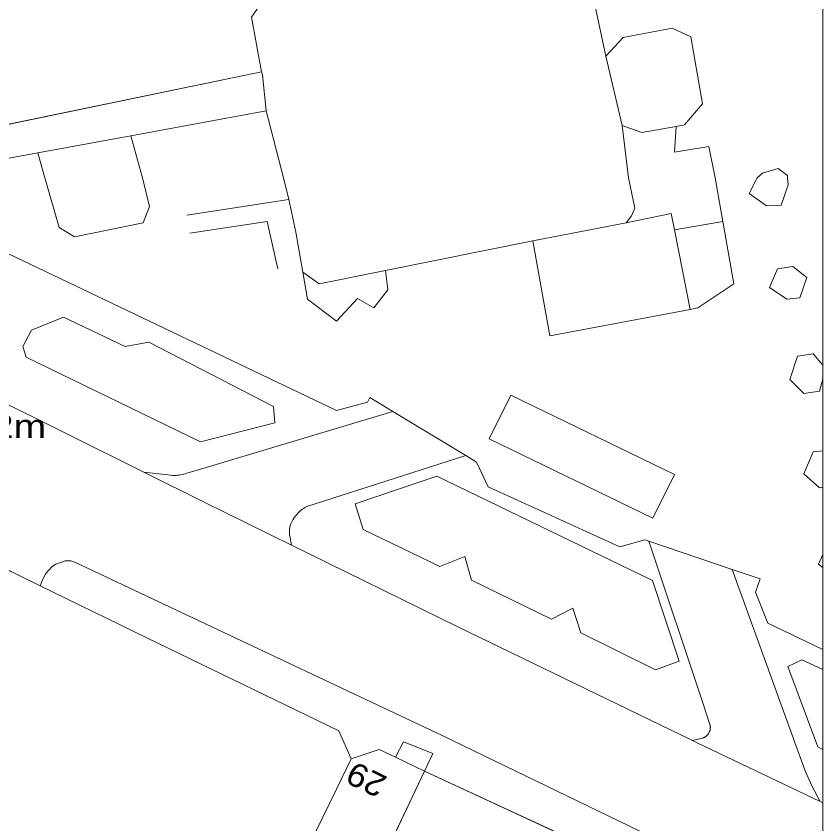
# Model space of a CAD drawing. Extents: x 528790 to 529292, y 179350 to 179856.
# Drawn here: x 529238.4 to 529290.2, y 179458.5 to 179510.4 of the extents above; entities that cross this region are included whole.
import ezdxf

# ---------------------------------------------------------------- set-up
doc = ezdxf.new("R2010")
doc.units = 0
doc.header["$LTSCALE"] = 0.6
for name, color, linetype, lineweight in [('1', 7, 'Continuous', 13), ('2', 7, 'Continuous', 13), ('7', 7, 'Continuous', 13)]:
    doc.layers.add(name, color=color, linetype=linetype, lineweight=lineweight)
doc.layers.add('5', color=7, linetype='Continuous')

msp = doc.modelspace()

# ---------------------------------------------------------------- linework, layer by layer
at = {"layer": '1'}
for points in [[(529290.22, 179480.144), (529290, 179480.1), (529289, 179481), (529289.6, 179482.4), (529290.22, 179482.462), (529290.22, 179487.099), (529290, 179486.3), (529289, 179486.15), (529288.1, 179487.05), (529288.6, 179488.55), (529289.6, 179488.7), (529290.22, 179487.963), (529290.22, 179512.837)], [(529236.8, 179503.2), (529254.2, 179506.8), (529253.55, 179510.3), (529254, 179510.95)], [(529254, 179510.95), (529253.55, 179510.3), (529254.2, 179506.8), (529254.25, 179506.6), (529254.5, 179504.3), (529255.6, 179500), (529255.95, 179498.6), (529256.4, 179496.5), (529256.85, 179493.95), (529257.9, 179493.2), (529262.15, 179494.05), (529271.6, 179495.95), (529277.6, 179497.1), (529277.95, 179497.55), (529278.15, 179498.05), (529277.75, 179500), (529277.35, 179503.35), (529276.3, 179507.8), (529275.7, 179510.6)], [(529275.7, 179510.6), (529276.3, 179507.8), (529277.4, 179509), (529280.55, 179509.6), (529281.75, 179509.05), (529282.5, 179504.75), (529281.35, 179503.4), (529280.8, 179503.3), (529280.7, 179501.65), (529281.35, 179501.75), (529282.9, 179502), (529283.3, 179500), (529283.4, 179499.5), (529283.8, 179497.2), (529284.5, 179493.2), (529282.2, 179491.65), (529281.7, 179491.55), (529272.7, 179489.85), (529271.6, 179495.95), (529262.15, 179494.05), (529262.3, 179492.8), (529261.4, 179491.65), (529260.35, 179492.25), (529259, 179490.8), (529257.15, 179492.2), (529256.85, 179493.95), (529256.4, 179496.5), (529255.95, 179498.6), (529255.6, 179500), (529254.5, 179504.3), (529245.8, 179502.7), (529246.55, 179500), (529247, 179498.15), (529246.6, 179497.1), (529242.2, 179496.2), (529241.2, 179496.8), (529240.3, 179500), (529239.85, 179501.6), (529235.2, 179500.75)], [(529233.6, 179497.2), (529259, 179485.05), (529261, 179485.6), (529261.15, 179485.9), (529262.63, 179485.003), (529267.306, 179482.17), (529268, 179481.75), (529268.75, 179480.15), (529277.2, 179476.3), (529278.8, 179476.75)], [(529236.7, 179486.05), (529246.643, 179481.097), (529248.385, 179480.899), (529248.482, 179480.892), (529248.579, 179480.89), (529248.716, 179480.893), (529248.813, 179480.901), (529248.91, 179480.912), (529249.006, 179480.928), (529249.101, 179480.947), (529249.196, 179480.971), (529249.289, 179480.998), (529249.406, 179481.038), (529250.208, 179481.278), (529262.63, 179485.003), (529261.15, 179485.9), (529261, 179485.6), (529259, 179485.05), (529233.6, 179497.2)], [(529290.22, 179452.774), (529290.22, 179459.873), (529290.053, 179459.953), (529282.2, 179463.7), (529281.852, 179463.869), (529266.75, 179471.2), (529256.119, 179476.417), (529250.55, 179479.15), (529246.643, 179481.097), (529236.7, 179486.05)], [(529278.8, 179476.75), (529279.06, 179476.662), (529284.405, 179474.857), (529286.2, 179474.25), (529285.9, 179473.4), (529286.7, 179471.4), (529290.22, 179469.708), (529290.22, 179474.977), (529289.95, 179475.2), (529290.22, 179475.808), (529290.22, 179480.144)], [(529255.002, 179452.549), (529259, 179460.75), (529259.95, 179462.7), (529259.15, 179464.5), (529246.844, 179470.476), (529240, 179473.8), (529236.4, 179475.55), (529234.9, 179472.4), (529229.655, 179460.856), (529228.098, 179457.563)], [(529236.4, 179475.55), (529240, 179473.8), (529240.15, 179474.2), (529240.35, 179474.6), (529240.55, 179474.8), (529240.75, 179475.05), (529241, 179475.2), (529241.6, 179475.4), (529241.95, 179475.4), (529242.25, 179475.3), (529265.8, 179464.2), (529281.8, 179456.45)], [(529281.8, 179456.45), (529265.8, 179464.2), (529242.25, 179475.3), (529241.95, 179475.4), (529241.6, 179475.4), (529241, 179475.2), (529240.75, 179475.05), (529240.55, 179474.8), (529240.35, 179474.6), (529240.15, 179474.2), (529240, 179473.8), (529246.844, 179470.476), (529259.15, 179464.5), (529259.95, 179462.7), (529261.75, 179463.3), (529262.8, 179462.8), (529263.3, 179463.8), (529265.2, 179463.05), (529264.65, 179461.9), (529284.55, 179452.7)]]:
    msp.add_lwpolyline(points, dxfattribs=at)
for points in [[(529280.8, 179503.3), (529281.35, 179503.4), (529282.5, 179504.75), (529281.75, 179509.05), (529280.55, 179509.6), (529277.4, 179509), (529276.3, 179507.8), (529277.35, 179503.35), (529278.6, 179502.9)], [(529239.85, 179501.6), (529245.8, 179502.7), (529254.5, 179504.3), (529254.25, 179506.6), (529254.2, 179506.8), (529236.8, 179503.2), (529235.8, 179503), (529234.8, 179507.8), (529233.9, 179507.65), (529231.45, 179507.15), (529228.15, 179506.5), (529229.25, 179500.7), (529229.4, 179500), (529229.8, 179499), (529232.6, 179497.8), (529234.15, 179498.15), (529234.2, 179497.9), (529234.35, 179497.15), (529235.9, 179497.3), (529235.4, 179500), (529235.2, 179500.75)], [(529283.8, 179497.2), (529283.4, 179499.5), (529283.3, 179500), (529282.9, 179502), (529281.35, 179501.75), (529280.7, 179501.65), (529280.8, 179503.3), (529278.6, 179502.9), (529277.35, 179503.35), (529277.75, 179500), (529278.15, 179498.05), (529277.95, 179497.55), (529277.6, 179497.1), (529280.49, 179497.7), (529280.7, 179496.65)], [(529246.6, 179497.1), (529247, 179498.15), (529246.55, 179500), (529245.8, 179502.7), (529239.85, 179501.6), (529240.3, 179500), (529241.2, 179496.8), (529242.2, 179496.2)], [(529286, 179500), (529285.5, 179499), (529286.6, 179498.2), (529287.55, 179498.25), (529288, 179499.55), (529287.95, 179500), (529287.95, 179500.15), (529287.35, 179500.6), (529286.35, 179500.3)], [(529285.5, 179499), (529286, 179500), (529286.35, 179500.3), (529287.35, 179500.6), (529287.95, 179500.15), (529287.95, 179500), (529288, 179499.55), (529287.55, 179498.25), (529286.6, 179498.2)], [(529272.7, 179489.85), (529281.7, 179491.55), (529280.7, 179496.65), (529280.49, 179497.7), (529277.6, 179497.1), (529271.6, 179495.95)], [(529280.7, 179496.65), (529281.7, 179491.55), (529282.2, 179491.65), (529284.5, 179493.2), (529283.8, 179497.2)], [(529262.15, 179494.05), (529257.9, 179493.2), (529256.85, 179493.95), (529257.15, 179492.2), (529259, 179490.8), (529260.35, 179492.25), (529261.4, 179491.65), (529262.3, 179492.8)], [(529288.75, 179492.3), (529289.2, 179493.6), (529288.3, 179494.3), (529287.3, 179494.15), (529286.8, 179492.95), (529287.9, 179492.2)], [(529286.8, 179492.95), (529287.3, 179494.15), (529288.3, 179494.3), (529289.2, 179493.6), (529288.75, 179492.3), (529287.9, 179492.2)], [(529241.491, 179491.057), (529239.425, 179490.207), (529238.882, 179489.164), (529239.096, 179488.475), (529250.285, 179483.053), (529255.045, 179484.276), (529254.966, 179485.313), (529246.971, 179489.452), (529245.452, 179489.16)], [(529241.491, 179491.057), (529245.452, 179489.16), (529246.971, 179489.452), (529254.966, 179485.313), (529255.045, 179484.276), (529250.285, 179483.053), (529239.096, 179488.475), (529238.882, 179489.164), (529239.425, 179490.207)], [(529290.22, 179487.963), (529289.6, 179488.7), (529288.6, 179488.55), (529288.1, 179487.05), (529289, 179486.15), (529290, 179486.3), (529290.22, 179487.099)], [(529270.2, 179486.05), (529280.7, 179480.95), (529279.3, 179478.15), (529268.8, 179483.25)], [(529279.3, 179478.15), (529280.7, 179480.95), (529270.2, 179486.05), (529268.8, 179483.25)], [(529267.306, 179482.17), (529262.63, 179485.003), (529250.208, 179481.278), (529249.406, 179481.038), (529249.289, 179480.998), (529249.196, 179480.971), (529249.101, 179480.947), (529249.006, 179480.928), (529248.91, 179480.912), (529248.813, 179480.901), (529248.716, 179480.893), (529248.579, 179480.89), (529248.482, 179480.892), (529248.385, 179480.899), (529246.643, 179481.097), (529250.55, 179479.15), (529256.119, 179476.417), (529256.005, 179477.017), (529255.996, 179477.08), (529255.99, 179477.143), (529255.986, 179477.207), (529255.985, 179477.271), (529255.987, 179477.334), (529255.991, 179477.398), (529255.998, 179477.461), (529256.008, 179477.524), (529256.02, 179477.587), (529256.035, 179477.649), (529256.052, 179477.71), (529256.078, 179477.785), (529256.116, 179477.875), (529256.16, 179477.962), (529256.21, 179478.047), (529256.316, 179478.205), (529256.375, 179478.283), (529256.436, 179478.359), (529256.501, 179478.433), (529256.569, 179478.503), (529256.64, 179478.571), (529256.714, 179478.635), (529256.79, 179478.697), (529256.869, 179478.755), (529256.95, 179478.81), (529257.104, 179478.902)], [(529290.22, 179480.144), (529290.22, 179482.462), (529289.6, 179482.4), (529289, 179481), (529290, 179480.1)], [(529268, 179481.75), (529267.306, 179482.17), (529257.104, 179478.902), (529256.95, 179478.81), (529256.869, 179478.755), (529256.79, 179478.697), (529256.714, 179478.635), (529256.64, 179478.571), (529256.569, 179478.503), (529256.501, 179478.433), (529256.436, 179478.359), (529256.375, 179478.283), (529256.316, 179478.205), (529256.21, 179478.047), (529256.16, 179477.962), (529256.116, 179477.875), (529256.078, 179477.785), (529256.052, 179477.71), (529256.035, 179477.649), (529256.02, 179477.587), (529256.008, 179477.524), (529255.998, 179477.461), (529255.991, 179477.398), (529255.987, 179477.334), (529255.985, 179477.271), (529255.986, 179477.207), (529255.99, 179477.143), (529255.996, 179477.08), (529256.005, 179477.017), (529256.119, 179476.417), (529266.75, 179471.2), (529281.852, 179463.869), (529282.477, 179464.019), (529282.506, 179464.028), (529282.536, 179464.039), (529282.565, 179464.051), (529282.593, 179464.064), (529282.621, 179464.078), (529282.648, 179464.093), (529282.675, 179464.11), (529282.7, 179464.127), (529282.725, 179464.146), (529282.749, 179464.166), (529282.773, 179464.187), (529282.795, 179464.209), (529282.817, 179464.231), (529282.837, 179464.255), (529282.857, 179464.279), (529282.875, 179464.305), (529282.892, 179464.331), (529282.908, 179464.358), (529282.927, 179464.394), (529282.94, 179464.422), (529282.952, 179464.451), (529282.962, 179464.481), (529282.972, 179464.511), (529282.98, 179464.541), (529282.986, 179464.571), (529282.992, 179464.602), (529282.996, 179464.633), (529282.998, 179464.664), (529283, 179464.695), (529283, 179464.727), (529282.998, 179464.758), (529282.996, 179464.789), (529282.992, 179464.82), (529282.986, 179464.851), (529282.98, 179464.881), (529282.972, 179464.911), (529282.534, 179466.227), (529279.06, 179476.662), (529278.8, 179476.75), (529277.2, 179476.3), (529268.75, 179480.15)], [(529260.716, 179477.416), (529260.215, 179479.071), (529265.454, 179480.852), (529279.283, 179474.142), (529280.995, 179468.972), (529279.479, 179468.404), (529274.683, 179470.777), (529274.183, 179472.363), (529272.807, 179471.657), (529267.664, 179474.165), (529267.234, 179475.683), (529265.65, 179475.044)], [(529265.454, 179480.852), (529260.215, 179479.071), (529260.716, 179477.416), (529265.65, 179475.044), (529267.234, 179475.683), (529267.664, 179474.165), (529272.807, 179471.657), (529274.183, 179472.363), (529274.683, 179470.777), (529279.479, 179468.404), (529280.995, 179468.972), (529279.283, 179474.142)], [(529289.512, 179460.965), (529289.087, 179461.929), (529288.596, 179463.286), (529284.405, 179474.857), (529279.06, 179476.662), (529282.534, 179466.227), (529282.972, 179464.911), (529282.98, 179464.881), (529282.986, 179464.851), (529282.992, 179464.82), (529282.996, 179464.789), (529282.998, 179464.758), (529283, 179464.727), (529283, 179464.695), (529282.998, 179464.664), (529282.996, 179464.633), (529282.992, 179464.602), (529282.986, 179464.571), (529282.98, 179464.541), (529282.972, 179464.511), (529282.962, 179464.481), (529282.952, 179464.451), (529282.94, 179464.422), (529282.927, 179464.394), (529282.908, 179464.358), (529282.892, 179464.331), (529282.875, 179464.305), (529282.857, 179464.279), (529282.837, 179464.255), (529282.817, 179464.231), (529282.795, 179464.209), (529282.773, 179464.187), (529282.749, 179464.166), (529282.725, 179464.146), (529282.7, 179464.127), (529282.675, 179464.11), (529282.648, 179464.093), (529282.621, 179464.078), (529282.593, 179464.064), (529282.565, 179464.051), (529282.536, 179464.039), (529282.506, 179464.028), (529282.477, 179464.019), (529281.852, 179463.869), (529282.2, 179463.7), (529290.053, 179459.953)], [(529290.22, 179474.977), (529290.22, 179475.808), (529289.95, 179475.2)], [(529290.22, 179459.873), (529290.22, 179463.302), (529289.902, 179463.459), (529287.983, 179468.627), (529288.878, 179469.051), (529290.22, 179468.424), (529290.22, 179469.708), (529286.7, 179471.4), (529285.9, 179473.4), (529286.2, 179474.25), (529284.405, 179474.857), (529288.596, 179463.286), (529289.087, 179461.929), (529289.512, 179460.965), (529290.053, 179459.953)], [(529290.22, 179463.302), (529290.22, 179468.424), (529288.878, 179469.051), (529287.983, 179468.627), (529289.902, 179463.459)], [(529264.65, 179461.9), (529265.2, 179463.05), (529263.3, 179463.8), (529262.8, 179462.8)], [(529262.8, 179462.8), (529261.75, 179463.3), (529259.95, 179462.7), (529259, 179460.75), (529255.002, 179452.549), (529254.218, 179450.942), (529253.448, 179449.363), (529249.795, 179441.859), (529246.7, 179435.5), (529251.2, 179433.4), (529253.35, 179438), (529264.65, 179461.9)], [(529285.8, 179449.3), (529284.55, 179452.7), (529264.65, 179461.9), (529253.35, 179438), (529258.8, 179435.6), (529263.3, 179433.55), (529264.2, 179435.55), (529265.6, 179434.9), (529266, 179435.7), (529267.4, 179435.05), (529267, 179434.25), (529271.4, 179432.25), (529273.9, 179431.15), (529280.4, 179439.3), (529279.75, 179439.65), (529280.2, 179439.8), (529280.7, 179440.25), (529280.95, 179440.45), (529281.3, 179440.8), (529281.4, 179441.15), (529281.6, 179441.45), (529281.6, 179442.5), (529282.35, 179442.1)]]:
    msp.add_lwpolyline(points, close=True, dxfattribs=at)
at = {"layer": '2'}
for p, q in [((529276.3, 179507.8), (529277.35, 179503.35)), ((529236.8, 179503.2), (529254.2, 179506.8)), ((529254.25, 179506.6), (529254.2, 179506.8)), ((529254.5, 179504.3), (529254.25, 179506.6)), ((529254.5, 179504.3), (529245.8, 179502.7)), ((529245.8, 179502.7), (529239.85, 179501.6)), ((529255.95, 179498.6), (529249.4, 179497.6)), ((529255.95, 179498.6), (529256.4, 179496.5)), ((529277.6, 179497.1), (529271.6, 179495.95)), ((529283.8, 179497.2), (529280.7, 179496.65)), ((529256.85, 179493.95), (529256.4, 179496.5)), ((529280.7, 179496.65), (529281.7, 179491.55)), ((529271.6, 179495.95), (529262.15, 179494.05)), ((529267.306, 179482.17), (529262.63, 179485.003)), ((529290.22, 179480.144), (529290, 179480.1)), ((529284.405, 179474.857), (529279.06, 179476.662)), ((529236.4, 179475.55), (529240, 179473.8)), ((529262.8, 179462.8), (529264.65, 179461.9)), ((529264.65, 179461.9), (529253.35, 179438)), ((529264.65, 179461.9), (529284.55, 179452.7)), ((529290.053, 179459.953), (529290.22, 179459.873))]:
    msp.add_line(p, q, dxfattribs=at)
for points in [[(529254.2, 179506.8), (529253.55, 179510.3), (529254, 179510.95), (529264.9, 179513.05), (529264.75, 179514.15), (529268, 179514.7), (529268.2, 179513.6), (529274.35, 179514.9), (529274.6, 179514.8), (529274.75, 179514.7), (529274.8, 179514.55), (529275.7, 179510.6), (529276.3, 179507.8)], [(529276.3, 179507.8), (529277.4, 179509), (529280.55, 179509.6), (529281.75, 179509.05), (529282.5, 179504.75), (529281.35, 179503.4), (529280.8, 179503.3)], [(529254.5, 179504.3), (529255.6, 179500), (529255.95, 179498.6)], [(529277.35, 179503.35), (529277.75, 179500), (529278.15, 179498.05), (529277.95, 179497.55), (529277.6, 179497.1)], [(529280.8, 179503.3), (529278.6, 179502.9), (529277.35, 179503.35)], [(529283.8, 179497.2), (529283.4, 179499.5), (529283.3, 179500), (529282.9, 179502), (529281.35, 179501.75), (529280.7, 179501.65), (529280.8, 179503.3)], [(529239.85, 179501.6), (529240.3, 179500), (529241.2, 179496.8), (529242.2, 179496.2), (529246.6, 179497.1), (529247, 179498.15), (529246.55, 179500), (529245.8, 179502.7)], [(529239.85, 179501.6), (529235.2, 179500.75), (529235.4, 179500), (529235.9, 179497.3), (529234.35, 179497.15), (529234.2, 179497.9)], [(529262.63, 179485.003), (529261.15, 179485.9), (529261, 179485.6), (529259, 179485.05), (529233.6, 179497.2), (529234.2, 179497.9)], [(529280.7, 179496.65), (529280.49, 179497.7), (529277.6, 179497.1)], [(529249.6, 179496.45), (529254.55, 179497.2), (529255.25, 179494.15)], [(529283.8, 179497.2), (529284.5, 179493.2), (529282.2, 179491.65), (529281.7, 179491.55)], [(529281.7, 179491.55), (529272.7, 179489.85), (529271.6, 179495.95)], [(529262.15, 179494.05), (529262.3, 179492.8), (529261.4, 179491.65), (529260.35, 179492.25), (529259, 179490.8), (529257.15, 179492.2), (529256.85, 179493.95)], [(529262.15, 179494.05), (529257.9, 179493.2), (529256.85, 179493.95)], [(529222.455, 179493.382), (529225.55, 179491.8), (529236.7, 179486.05), (529246.643, 179481.097)], [(529289, 179486.15), (529288.1, 179487.05), (529288.6, 179488.55), (529289.6, 179488.7), (529290.22, 179487.963)], [(529290.22, 179487.099), (529290, 179486.3), (529289, 179486.15)], [(529246.643, 179481.097), (529248.385, 179480.899), (529248.482, 179480.892), (529248.579, 179480.89), (529248.716, 179480.893), (529248.813, 179480.901), (529248.91, 179480.912), (529249.006, 179480.928), (529249.101, 179480.947), (529249.196, 179480.971), (529249.289, 179480.998), (529249.406, 179481.038), (529250.208, 179481.278), (529262.63, 179485.003)], [(529290, 179480.1), (529289, 179481), (529289.6, 179482.4), (529290.22, 179482.462)], [(529256.119, 179476.417), (529256.005, 179477.017), (529255.996, 179477.08), (529255.99, 179477.143), (529255.986, 179477.207), (529255.985, 179477.271), (529255.987, 179477.334), (529255.991, 179477.398), (529255.998, 179477.461), (529256.008, 179477.524), (529256.02, 179477.587), (529256.035, 179477.649), (529256.052, 179477.71), (529256.078, 179477.785), (529256.116, 179477.875), (529256.16, 179477.962), (529256.21, 179478.047), (529256.316, 179478.205), (529256.375, 179478.283), (529256.436, 179478.359), (529256.501, 179478.433), (529256.569, 179478.503), (529256.64, 179478.571), (529256.714, 179478.635), (529256.79, 179478.697), (529256.869, 179478.755), (529256.95, 179478.81), (529257.104, 179478.902), (529267.306, 179482.17)], [(529279.06, 179476.662), (529278.8, 179476.75), (529277.2, 179476.3), (529268.75, 179480.15), (529268, 179481.75), (529267.306, 179482.17)], [(529246.643, 179481.097), (529250.55, 179479.15), (529256.119, 179476.417)], [(529256.119, 179476.417), (529266.75, 179471.2), (529281.852, 179463.869)], [(529279.06, 179476.662), (529282.534, 179466.227), (529282.972, 179464.911), (529282.98, 179464.881), (529282.986, 179464.851), (529282.992, 179464.82), (529282.996, 179464.789), (529282.998, 179464.758), (529283, 179464.727), (529283, 179464.695), (529282.998, 179464.664), (529282.996, 179464.633), (529282.992, 179464.602), (529282.986, 179464.571), (529282.98, 179464.541), (529282.972, 179464.511), (529282.962, 179464.481), (529282.952, 179464.451), (529282.94, 179464.422), (529282.927, 179464.394), (529282.908, 179464.358), (529282.892, 179464.331), (529282.875, 179464.305), (529282.857, 179464.279), (529282.837, 179464.255), (529282.817, 179464.231), (529282.795, 179464.209), (529282.773, 179464.187), (529282.749, 179464.166), (529282.725, 179464.146), (529282.7, 179464.127), (529282.675, 179464.11), (529282.648, 179464.093), (529282.621, 179464.078), (529282.593, 179464.064), (529282.565, 179464.051), (529282.536, 179464.039), (529282.506, 179464.028), (529282.477, 179464.019), (529281.852, 179463.869)], [(529290.22, 179474.977), (529289.95, 179475.2), (529290.22, 179475.808)], [(529240, 179473.8), (529240.15, 179474.2), (529240.35, 179474.6), (529240.55, 179474.8), (529240.75, 179475.05), (529241, 179475.2), (529241.6, 179475.4), (529241.95, 179475.4), (529242.25, 179475.3), (529265.8, 179464.2), (529281.8, 179456.45), (529289.2, 179453), (529289.4, 179452.8), (529289.6, 179452.65), (529289.75, 179452.5), (529289.95, 179452.2)], [(529284.405, 179474.857), (529288.596, 179463.286), (529289.087, 179461.929), (529289.512, 179460.965), (529290.053, 179459.953)], [(529290.22, 179469.708), (529286.7, 179471.4), (529285.9, 179473.4), (529286.2, 179474.25), (529284.405, 179474.857)], [(529259.95, 179462.7), (529259.15, 179464.5), (529246.844, 179470.476), (529240, 179473.8)], [(529290.22, 179463.302), (529289.902, 179463.459), (529287.983, 179468.627), (529288.878, 179469.051), (529290.22, 179468.424)], [(529262.8, 179462.8), (529263.3, 179463.8), (529265.2, 179463.05), (529264.65, 179461.9)], [(529281.852, 179463.869), (529282.2, 179463.7), (529290.053, 179459.953)], [(529259.95, 179462.7), (529261.75, 179463.3), (529262.8, 179462.8)], [(529246.7, 179435.5), (529249.795, 179441.859), (529253.448, 179449.363), (529254.218, 179450.942), (529255.002, 179452.549), (529259, 179460.75), (529259.95, 179462.7)]]:
    msp.add_lwpolyline(points, dxfattribs=at)
for points in [[(529286, 179500), (529285.5, 179499), (529286.6, 179498.2), (529287.55, 179498.25), (529288, 179499.55), (529287.95, 179500), (529287.95, 179500.15), (529287.35, 179500.6), (529286.35, 179500.3)], [(529288.75, 179492.3), (529287.9, 179492.2), (529286.8, 179492.95), (529287.3, 179494.15), (529288.3, 179494.3), (529289.2, 179493.6)], [(529250.285, 179483.053), (529239.096, 179488.475), (529238.882, 179489.164), (529239.425, 179490.207), (529241.491, 179491.057), (529245.452, 179489.16), (529246.971, 179489.452), (529254.966, 179485.313), (529255.045, 179484.276)], [(529279.3, 179478.15), (529268.8, 179483.25), (529270.2, 179486.05), (529280.7, 179480.95)], [(529279.479, 179468.404), (529274.683, 179470.777), (529274.183, 179472.363), (529272.807, 179471.657), (529267.664, 179474.165), (529267.234, 179475.683), (529265.65, 179475.044), (529260.716, 179477.416), (529260.215, 179479.071), (529265.454, 179480.852), (529279.283, 179474.142), (529280.995, 179468.972)]]:
    msp.add_lwpolyline(points, close=True, dxfattribs=at)
at = {"layer": '7'}
msp.add_lwpolyline([(528790.22, 179356.024), (529290.22, 179356.024), (529290.22, 179856.024), (528790.22, 179856.024)], close=True, dxfattribs=at)

# ---------------------------------------------------------------- texts
at = {"layer": '5', "width": 1.25}
msp.add_text('4.2m', height=1.5, dxfattribs=at).set_placement((529234.8, 179483.3))
at = {"layer": '5', "width": 1.1}
msp.add_text('29', height=1.5, rotation=154, dxfattribs=at).set_placement((529262.35, 179461.5))

doc.saveas('drawing.dxf')
